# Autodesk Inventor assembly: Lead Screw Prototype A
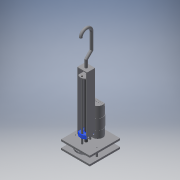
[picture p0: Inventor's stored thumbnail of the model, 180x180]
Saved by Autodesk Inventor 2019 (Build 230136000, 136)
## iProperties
Created: 2018-09
Part Number: Lead Screw Prototype A
Document SubType Name: Assembly
Designer: drawing
Author: drawing
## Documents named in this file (18)
- Z:\Sadler\Austin\Lead Screw Prototype A.iam
- Z:\Sadler\Austin\Part3.ipt
- Z:\Sadler\Austin\Robot\ActoBotics Bearing .375.ipt
- Z:\Sadler\Austin\COTSParts\Tetrix\Tetrix Gear 80T.ipt
- Z:\Sadler\Austin\Part2.ipt
- Z:\Sadler\Austin\COTSParts\Tetrix\Tetrix Gear 40T.ipt
- Z:\Sadler\Austin\Part6.ipt
- Z:\Sadler\Austin\Part5.ipt
- Z:\Sadler\Austin\COTSParts\Motors\Andymark 2964  NeveRest 40 Motor.ipt
- \\Smc-dc16\users\drawing\My Documents\Inventor\Content Center Files\R2019\en-US\AS 1420\AS 1420 - 1973 - M3 x 6.ipt
- \\Smc-dc16\users\drawing\My Documents\Inventor\Content Center Files\R2019\en-US\ANSI B18.3(05)\ANSI B18.3 - 6-32 UNC - 0.5(31).ipt
- Z:\Sadler\Austin\Part9.ipt
- Z:\Sadler\Austin\95082A641.iam
- Z:\Sadler\Austin\COTSParts\Tetrix\Tetrix Hub - axle.ipt
- Z:\Sadler\Austin\COTSParts\Tetrix\Tetrix hub - motor.ipt
- Z:\Sadler\Austin\Part11.ipt
- \\Smc-dc16\users\drawing\My Documents\Inventor\Content Center Files\R2019\en-US\ANSI B18.3(05)\ANSI B18.3 - 1_4-20 UNC - 0.75(31).ipt
- Z:\Sadler\Austin\Part12.ipt
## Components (29 placed, 17 different names)
1. Part3:1 — Insert:1, Insert:7, Mate:3, Insert:10, Insert:11, Insert:13, Insert:14, Mate:8, Mate:9, Mate:10, Insert:15, Insert:16, Insert:17, Insert:18, Insert:19, Insert:20, Insert:21, Insert:22, Angle:1
2. ActoBotics Bearing .375:1 — Insert:1, Mate:11
3. Part3:2 — Insert:9, Insert:12, Mate:4
4. ActoBotics Bearing .375:2 — Insert:9
5. Tetrix Gear 80T:1 — Mate:1, Flush:1, Insert:26
6. Part2:1 — Insert:7, Mate:1, Mate:4, Mate:12, Insert:31
7. Tetrix Gear 40T:1 — Mate:3, Flush:1, Insert:27
8. Part6:1 — Insert:10
9. Part6:2 — Insert:11, Insert:12
10. Part5:1 — Insert:13, Mate:5, Mate:13
11. Part5:2 — Insert:14, Mate:6
12. 95082A641:1 [sub-assembly] — Mate:5, Mate:6, Insert:28, Flush:2, Mate:12
13. Andymark 2964  NeveRest 40 Motor:1 — Mate:8, Mate:9, Mate:10
14. AS 1420 - Metric M3 x 6:1 — Insert:19
15. AS 1420 - Metric M3 x 6:2 — Insert:17
16. AS 1420 - Metric M3 x 6:3 — Insert:18
17. AS 1420 - Metric M3 x 6:4 — Insert:20
18. AS 1420 - Metric M3 x 6:5 — Insert:15
19. AS 1420 - Metric M3 x 6:6 — Insert:16
20. Hexagon Socket Head Cap Screw - Inch No. 6 - 32 UNC - 1/2:1 — Insert:21
21. Hexagon Socket Head Cap Screw - Inch No. 6 - 32 UNC - 1/2:2 — Insert:22
22. Part9:1 — Angle:1, Insert:29
23. Tetrix Hub - axle:1 — Insert:26, Mate:11
24. Tetrix hub - motor:1 — Insert:27
25. Part11:1 — Insert:28, Flush:2, Insert:29, Insert:30
26. Hexagon Socket Head Cap Screw - Inch 1/4 - 20 UNC - 3/4:1 — Insert:30
27. Part12:1 — Insert:31, Mate:13, Insert:32, Insert:33
28. Hexagon Socket Head Cap Screw - Inch No. 6 - 32 UNC - 1/2:3 — Insert:32
29. Hexagon Socket Head Cap Screw - Inch No. 6 - 32 UNC - 1/2:4 — Insert:33
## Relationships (38: Insert 24, Mate 11, Flush 2, Angle 1)
- Insert:1: Part3:1 ↔ ActoBotics Bearing .375:1
- Insert:7: Part3:1 ↔ Part2:1
- Mate:1: Tetrix Gear 80T:1 ↔ Part2:1
- Insert:9: Part3:2 ↔ ActoBotics Bearing .375:2
- Mate:3: Part3:1 ↔ Tetrix Gear 40T:1
- Flush:1: Tetrix Gear 80T:1 ↔ Tetrix Gear 40T:1
- Insert:10: Part3:1 ↔ Part6:1
- Insert:11: Part3:1 ↔ Part6:2
- Insert:12: Part3:2 ↔ Part6:2
- Mate:4: Part3:2 ↔ Part2:1
- Insert:13: Part3:1 ↔ Part5:1
- Insert:14: Part3:1 ↔ Part5:2
- Mate:5: Part5:1 ↔ 95082A641:1
- Mate:6: Part5:2 ↔ 95082A641:1
- Mate:8: Part3:1 ↔ Andymark 2964  NeveRest 40 Motor:1
- Mate:9: Part3:1 ↔ Andymark 2964  NeveRest 40 Motor:1
- Mate:10: Part3:1 ↔ Andymark 2964  NeveRest 40 Motor:1
- Insert:15: Part3:1 ↔ AS 1420 - Metric M3 x 6:5
- Insert:16: Part3:1 ↔ AS 1420 - Metric M3 x 6:6
- Insert:17: Part3:1 ↔ AS 1420 - Metric M3 x 6:2
- Insert:18: Part3:1 ↔ AS 1420 - Metric M3 x 6:3
- Insert:19: Part3:1 ↔ AS 1420 - Metric M3 x 6:1
- Insert:20: Part3:1 ↔ AS 1420 - Metric M3 x 6:4
- Insert:21: Part3:1 ↔ Hexagon Socket Head Cap Screw - Inch No. 6 - 32 UNC - 1/2:1
- Insert:22: Part3:1 ↔ Hexagon Socket Head Cap Screw - Inch No. 6 - 32 UNC - 1/2:2
- Angle:1: Part3:1 ↔ Part9:1
- Insert:26: Tetrix Gear 80T:1 ↔ Tetrix Hub - axle:1
- Insert:27: Tetrix Gear 40T:1 ↔ Tetrix hub - motor:1
- Mate:11: ActoBotics Bearing .375:1 ↔ Tetrix Hub - axle:1
- Insert:28: 95082A641:1 ↔ Part11:1
- Flush:2: 95082A641:1 ↔ Part11:1
- Insert:29: Part9:1 ↔ Part11:1
- Insert:30: Part11:1 ↔ Hexagon Socket Head Cap Screw - Inch 1/4 - 20 UNC - 3/4:1
- Mate:12: Part2:1 ↔ 95082A641:1
- Insert:31: Part2:1 ↔ Part12:1
- Mate:13: Part5:1 ↔ Part12:1
- Insert:32: Part12:1 ↔ Hexagon Socket Head Cap Screw - Inch No. 6 - 32 UNC - 1/2:3
- Insert:33: Part12:1 ↔ Hexagon Socket Head Cap Screw - Inch No. 6 - 32 UNC - 1/2:4
